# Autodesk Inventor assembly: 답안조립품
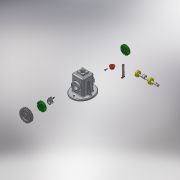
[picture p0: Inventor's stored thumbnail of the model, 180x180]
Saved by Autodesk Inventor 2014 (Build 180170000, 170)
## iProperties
Created: 2017-07
Part Number: 답안조립품
Document SubType Name: Assembly
Designer: user
Author: user
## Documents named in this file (16)
- C:\Users\user\Desktop\470708V1015\답안조립품.iam
- C:\Users\user\Desktop\470708V1015\V벨트풀리.ipt
- C:\Users\user\Desktop\470708V1015\고정핀 1.2 x  8.ipt
- C:\Users\user\Desktop\470708V1015\뒤커버.ipt
- C:\Users\user\Desktop\470708V1015\링크.ipt
- C:\Users\user\Desktop\470708V1015\멈춤나사 M3x8.ipt
- C:\Users\user\Desktop\470708V1015\베어링 12 x 32 x 10.ipt
- C:\Users\user\Desktop\470708V1015\본체.ipt
- C:\Users\user\Desktop\470708V1015\볼트 M4 x 12.ipt
- C:\Users\user\Desktop\470708V1015\부시.ipt
- C:\Users\user\Desktop\470708V1015\슬라이드.ipt
- C:\Users\user\Desktop\470708V1015\앞커버.ipt
- C:\Users\user\Desktop\470708V1015\오일실 12 25 7.ipt
- C:\Users\user\Desktop\470708V1015\키 4 x 4 x 10.ipt
- C:\Users\user\Desktop\470708V1015\편심축.ipt
- C:\Users\user\Desktop\470708V1015\핀 5 x 18.ipt
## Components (3 placed, 3 different names)
1. V벨트풀리:1
2. 고정핀 1.2 x  8:1
3. 핀 5 x 18:1 — 플러쉬:1
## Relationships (1: Flush 1)
- 플러쉬:1 [Flush]: 핀 5 x 18:1
